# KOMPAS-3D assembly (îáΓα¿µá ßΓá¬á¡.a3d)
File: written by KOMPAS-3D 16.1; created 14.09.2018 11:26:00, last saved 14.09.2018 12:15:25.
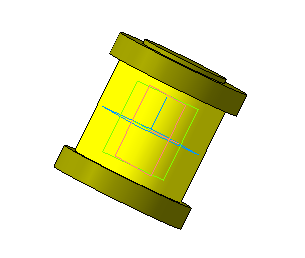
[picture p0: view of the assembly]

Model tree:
1. Сечение поверхностью:1

Referenced files in Z:\Мембранные насосы\Мембранный электропривод\А302-00.00.000 - ASTRA-302 (МЭ200)\3Д\Доработка\: Матрица стакан обечайка.m3d, Матрица стакан Заглушка.m3d, Матрица стакан Крышка.m3d
Referenced files in Z:\Мембранные насосы\Мембранный электропривод\А302-00.00.000 - ASTRA-302 (МЭ200)\3Д\: А302-00.10.002 3Д - Стакан.m3d
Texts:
  (ф) Матрица стакан  Обечайка
  (-) Матрица стакан  Заглушка
  (-) А302-00.10.002 3Д Стакан
  (-) Матрица стакан Крышка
